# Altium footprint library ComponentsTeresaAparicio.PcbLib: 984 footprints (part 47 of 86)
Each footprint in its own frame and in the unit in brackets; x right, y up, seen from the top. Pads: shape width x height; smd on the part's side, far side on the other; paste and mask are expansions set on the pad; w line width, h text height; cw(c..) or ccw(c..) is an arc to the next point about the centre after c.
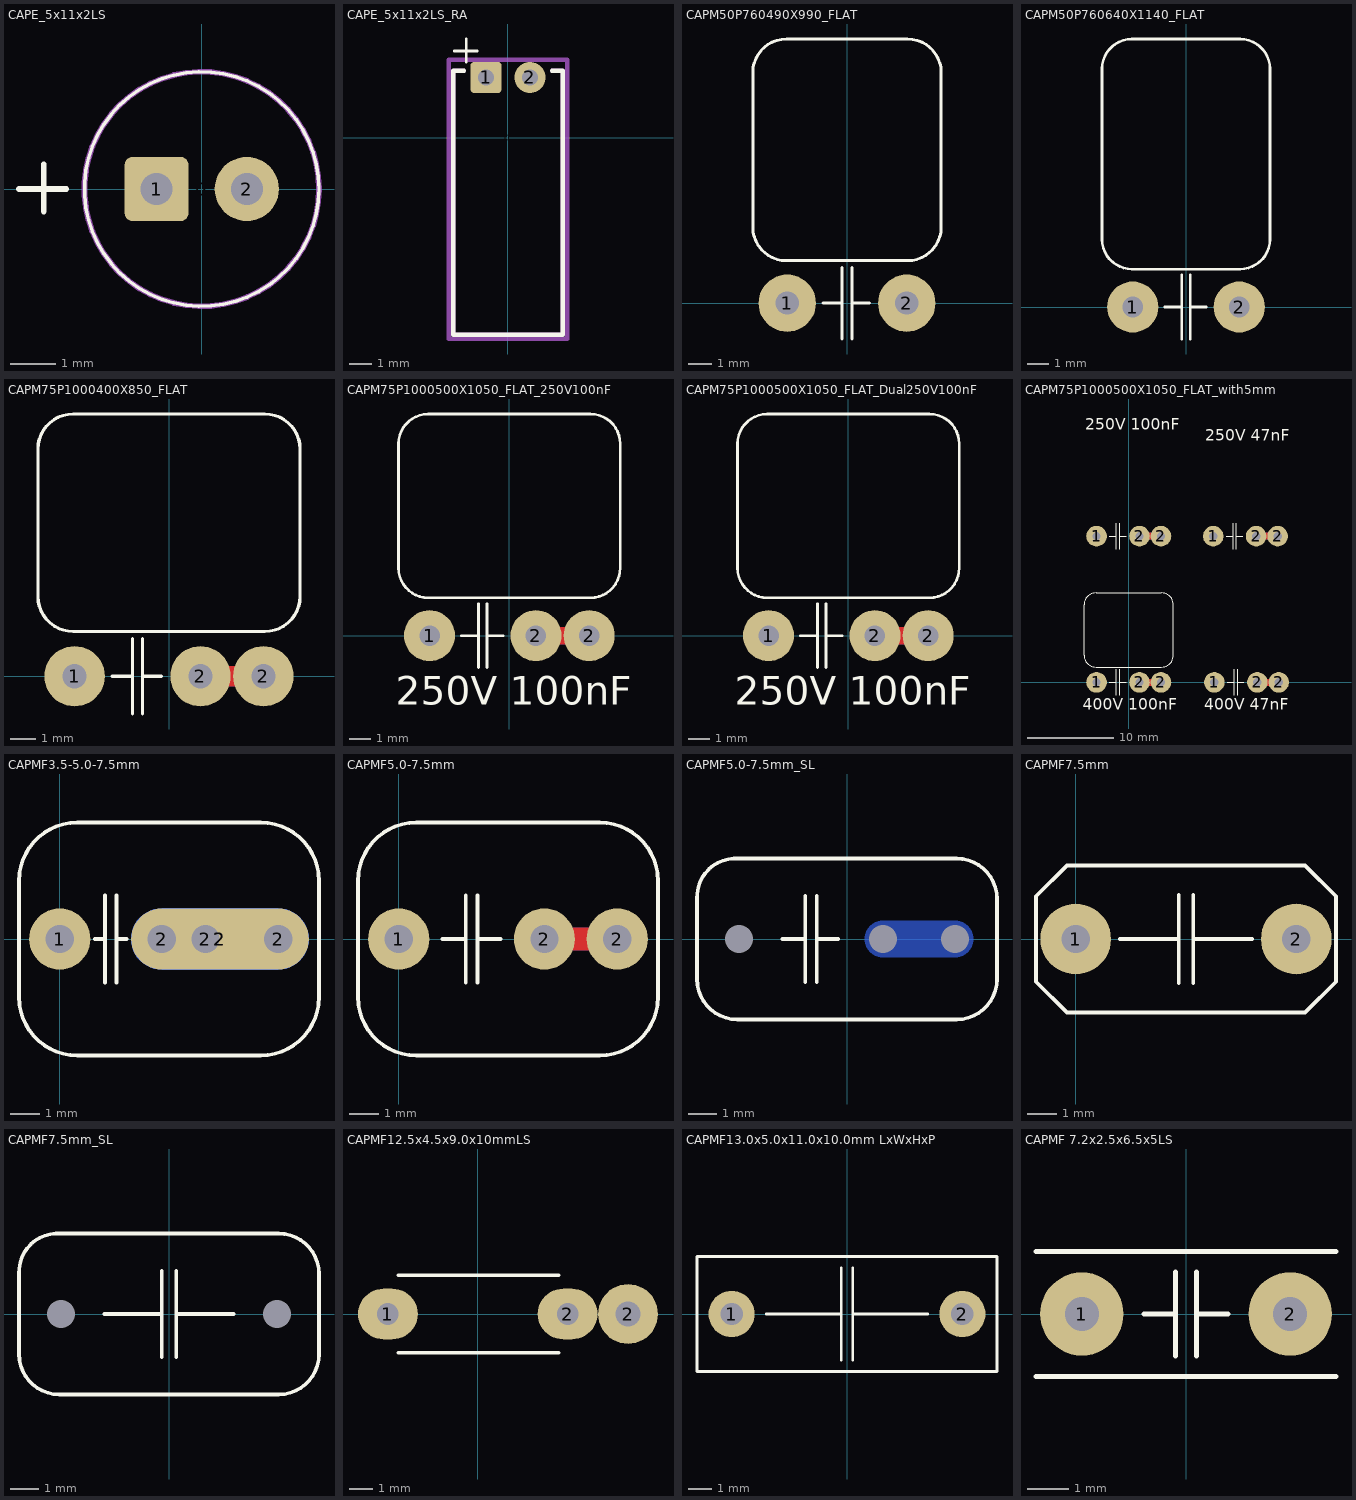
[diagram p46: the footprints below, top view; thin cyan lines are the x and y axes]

## CAPE_5x11x2LS [mil] "Capacitor, electrolytic, radial can"
height 433.07
pads (3):
  round 39.37 on Mech14: 0(0,0)
  rrect25% 56x56 hole 28: 1(-39.37,0)
  round 56 hole 28: 2(39.37,0)
Top Overlay:
  circle w3: c0,0 r102.36
  lines w5: -159.45,0 -118.11,0 ; -137.8,-19.68 -137.8,21.65
Mechanical 13:
  circle w5: c0,0 r102.36
3D body: height 433.07, standoff -86.61, extent -98.42,-98.42 98.43,98.43

## CAPE_5x11x2LS_RA [mm] "Capacitor, electrolytic, radial can, laid over"
height 5
pads (3):
  round 0.5 on Mech14: 0(0,0)
  rrect25% 1.422x1.422 hole 0.711: 1(-1,2.75)
  round 1.422 hole 0.711: 2(1,2.75)
Top Overlay:
  lines w0.127: -2.45,3.95 -1.4,3.95 ; -1.9,3.45 -1.9,4.5
  lines w0.2: -2,3.05 -2.5,3.05 -2.5,-8.95 0,-8.95 2.5,-8.95 2.5,3.05 2,3.05
Mechanical 13:
  lines w0.2: -2,3.05 -2.5,3.05 -2.5,-8.95 0,-8.95 2.5,-8.95 2.5,3.05 2,3.05
Mechanical 14:
  lines w0.2: -2.7,-9.15 2.7,-9.15 2.7,3.55 -2.7,3.55 -2.7,-9.15
3D body: height 5.1, standoff -2.2, extent -2.5,-8.947 2.5,3

## CAPM50P760490X990_FLAT [mm] "Capacitor, THT, Metallized Polyester Film with 7.2x4.5x9.5mm LxTxH"
height 4.9
pads (2):
  round 2.4 hole 0.965 unplated: 1(-2.5,0) 2(2.5,0)
Top Overlay:
  lines w0.127: -1,0 -0.2,0 ; -0.2,-1.5 -0.2,1.5 ; 0.2,-1.5 0.2,1.5 ; 0.2,0 0.95,0 ; -3.937,3.175 ccw(c-2.54,3.175) -2.54,1.778 2.54,1.778 ccw(c2.54,3.175) 3.937,3.175 3.937,9.652 ccw(c2.54,9.652) 2.54,11.049 -2.54,11.049 ccw(c-2.54,9.652) -3.937,9.652 -3.937,3.175
3D body: height 4.9, standoff -1.78, extent -3.8,-0.249 3.8,11

## CAPM50P760640X1140_FLAT [mm] "Capacitor, THT, Metallized Polyester Film with 6.0x11.0x7.2mm TxHxW"
height 6.4
pads (2):
  round 2.4 hole 0.965 unplated: 1(-2.5,0) 2(2.5,0)
Top Overlay:
  lines w0.127: -1,0 -0.2,0 ; -0.2,-1.5 -0.2,1.5 ; 0.2,-1.5 0.2,1.5 ; 0.2,0 0.95,0 ; -3.937,3.175 ccw(c-2.54,3.175) -2.54,1.778 2.54,1.778 ccw(c2.54,3.175) 3.937,3.175 3.937,11.176 ccw(c2.54,11.176) 2.54,12.573 -2.54,12.573 ccw(c-2.54,11.176) -3.937,11.176 -3.937,3.175
3D body: height 6.4, standoff -1.78, extent -3.8,-0.249 3.8,12.5

## CAPM75P1000400X850_FLAT [mm] "Capacitor, THT, Metallized Polyester Film with 3.5x9.5x10.0mm TxHxW"
height 3.5
pads (3):
  round 2.4 hole 0.965 unplated: 1(-3.75,0) 2(1.25,0) 2(3.75,0)
Top Layer:
  lines w0.813: 1.25,0 3.75,0
Bottom Layer:
  lines w0.813: 1.25,0 3.75,0
Top Overlay:
  lines w0.127: -2.25,0 -1.45,0 ; -1.45,-1.5 -1.45,1.5 ; -1.05,-1.5 -1.05,1.5 ; -1.05,0 -0.3,0 ; -5.207,3.175 ccw(c-3.81,3.175) -3.81,1.778 3.81,1.778 ccw(c3.81,3.175) 5.207,3.175 5.207,9.017 ccw(c3.81,9.017) 3.81,10.414 -3.81,10.414 ccw(c-3.81,9.017) -5.207,9.017 -5.207,3.175
3D body: height 4, standoff -1.78, extent -5,-0.249 5,9.6

## CAPM75P1000500X1050_FLAT_250V100nF [mm] "Capacitor, THT, Metallized Polyester Film with 3.5x9.5x10.0mm TxHxW"
height 3.5
pads (3):
  round 2.4 hole 0.965 unplated: 1(-3.75,0) 2(1.25,0) 2(3.75,0)
Top Layer:
  lines w0.813: 1.25,0 3.75,0
Bottom Layer:
  lines w0.813: 1.25,0 3.75,0
Top Overlay:
  lines w0.127: -2.25,0 -1.45,0 ; -1.45,-1.5 -1.45,1.5 ; -1.05,-1.5 -1.05,1.5 ; -1.05,0 -0.3,0 ; -5.207,3.175 ccw(c-3.81,3.175) -3.81,1.778 3.81,1.778 ccw(c3.81,3.175) 5.207,3.175 5.207,9.017 ccw(c3.81,9.017) 3.81,10.414 -3.81,10.414 ccw(c-3.81,9.017) -5.207,9.017 -5.207,3.175
  text "250V 100nF" at -5.334,-3.683 h2.29
3D body: height 4, standoff -1.78, extent -5,-0.249 5,9.6
3D body: height 4.5, standoff -1.78, extent -4.92,-0.249 2.38,10.6

## CAPM75P1000500X1050_FLAT_Dual250V100nF [mm] "Capacitor, THT, Metallized Polyester Film with 3.5x9.5x10.0mm TxHxW"
height 3.5
pads (3):
  round 2.4 hole 0.965 unplated: 1(-3.75,0) 2(1.25,0) 2(3.75,0)
Top Layer:
  lines w0.813: 1.25,0 3.75,0
Bottom Layer:
  lines w0.813: 1.25,0 3.75,0
Top Overlay:
  lines w0.127: -2.25,0 -1.45,0 ; -1.45,-1.5 -1.45,1.5 ; -1.05,-1.5 -1.05,1.5 ; -1.05,0 -0.3,0 ; -5.207,3.175 ccw(c-3.81,3.175) -3.81,1.778 3.81,1.778 ccw(c3.81,3.175) 5.207,3.175 5.207,9.017 ccw(c3.81,9.017) 3.81,10.414 -3.81,10.414 ccw(c-3.81,9.017) -5.207,9.017 -5.207,3.175
  text "250V 100nF" at -5.334,-3.683 h2.29
3D body: height 4.2, standoff -1.78, extent -4.5,-0.249 4.5,9.6
3D body: height 5.7, standoff -1.78, extent -4.5,-0.249 2,10.1
3D body: height 5.4, standoff -1.78, extent -5.05,-0.249 2.55,11.5
3D body: height 4.5, standoff -1.78, extent -4.9,-0.249 2.4,10.6
3D body: height 4, standoff -1.78, extent -5,-0.249 5,9.6

## CAPM75P1000500X1050_FLAT_with5mm [mm] "Capacitor, THT, Metallized Polyester Film with 3.5x9.5x10.0mm TxHxW"
height 3.5
pads (12):
  round 2.4 hole 0.965 unplated: 1(-3.75,0) 1(-3.75,17.018) 1(9.839,17.018) 1(9.966,0) 2(1.25,0) 2(1.25,17.018) 2(3.75,0) 2(3.75,17.018) 2(14.839,17.018) 2(14.966,0) 2(17.339,17.018) 2(17.466,0)
Top Layer:
  lines w0.813: 1.25,0 3.75,0 ; 1.25,17.018 3.75,17.018 ; 14.839,17.018 17.339,17.018 ; 14.966,0 17.466,0
Bottom Layer:
  lines w0.813: 1.25,0 3.75,0 ; 1.25,17.018 3.75,17.018 ; 14.839,17.018 17.339,17.018 ; 14.966,0 17.466,0
Top Overlay:
  lines w0.127: -2.25,0 -1.45,0 ; -2.25,17.018 -1.45,17.018 ; -1.45,-1.5 -1.45,1.5 ; -1.45,15.518 -1.45,18.518 ; -1.05,-1.5 -1.05,1.5 ; -1.05,0 -0.3,0 ; -1.05,15.518 -1.05,18.518 ; -1.05,17.018 -0.3,17.018 ; 11.339,17.018 12.139,17.018 ; 11.466,0 12.266,0 ; 12.139,15.518 12.139,18.518 ; 12.266,-1.5 12.266,1.5 ; 12.539,15.518 12.539,18.518 ; 12.539,17.018 13.289,17.018 ; 12.666,-1.5 12.666,1.5 ; 12.666,0 13.416,0 ; -5.207,3.175 ccw(c-3.81,3.175) -3.81,1.778 3.81,1.778 ccw(c3.81,3.175) 5.207,3.175 5.207,9.017 ccw(c3.81,9.017) 3.81,10.414 -3.81,10.414 ccw(c-3.81,9.017) -5.207,9.017 -5.207,3.175
  text "400V 100nF" at -5.334,-3.683 h2.29
  text "400V 47nF" at 8.763,-3.683 h2.29
  text "250V 100nF" at -5.08,28.956 h2.29
  text "250V 47nF" at 8.89,27.686 h2.29
3D body: height 4, standoff -1.78, extent -5,16.769 5,26.618
3D body: height 4.5, standoff -1.78, extent -4.92,16.769 2.38,27.618
3D body: height 3.5, standoff -1.78, extent 8.719,16.769 15.919,26.118
3D body: height 2.5, standoff -1.78, extent 8.589,16.769 18.589,25.118
3D body: height 4, standoff -1.78, extent 8.716,-0.249 18.716,9.6
3D body: height 4.5, standoff -1.78, extent 8.796,-0.249 16.096,10.6
3D body: height 5, standoff -1.78, extent -5,-0.249 5,11.6
3D body: height 7.8, standoff -1.78, extent -5.17,-0.249 2.63,14.1

## CAPMF3.5-5.0-7.5mm [mm] "Capacitor, THT, Metallized Polyester Film, 3.5 & 5.0 & 7.5mm pitch hybrid"
height 10
pads (6):
  round 2.1 hole 0.965: 1(0,0)
  round 1.5 hole 0.965: 2(3.5,0) 2(5,0) 2(7.5,0)
  oval 6.1x2.1 smd: 2(5.5,0)
  oval 6.1x2.1 smd far side: 2(5.5,0)
Top Overlay:
  lines w0.127: 1.2,0 1.55,0 ; 1.55,-1.5 1.55,1.5 ; 1.95,-1.5 1.95,1.5 ; 1.95,0 2.3,0 ; -1.4,-2 ccw(c0.6,-2) 0.6,-4 6.9,-4 ccw(c6.9,-2) 8.9,-2 8.9,2 ccw(c6.9,2) 6.9,4 0.6,4 ccw(c0.6,2) -1.4,2 -1.4,-2
3D body: height 11, standoff -2.54, extent -1.25,-4 8.75,4

## CAPMF5.0-7.5mm [mm] "Capacitor, THT, Metallized Polyester Film, 5 & 7.5mm pitch hybrid"
height 10
pads (3):
  round 2.1 hole 0.965: 1(0,0) 2(5,0) 2(7.5,0)
Top Layer:
  lines w0.8: 5,0 7.5,0
Bottom Layer:
  lines w0.8: 5,0 7.5,0
Top Overlay:
  lines w0.127: 1.5,0 2.3,0 ; 2.3,-1.5 2.3,1.5 ; 2.7,-1.5 2.7,1.5 ; 2.7,0 3.5,0 ; -1.4,-2 ccw(c0.6,-2) 0.6,-4 6.9,-4 ccw(c6.9,-2) 8.9,-2 8.9,2 ccw(c6.9,2) 6.9,4 0.6,4 ccw(c0.6,2) -1.4,2 -1.4,-2
3D body: height 11, standoff -2.54, extent -1.25,-4 8.75,4

## CAPMF5.0-7.5mm_SL [mm] "Capacitor, THT, Metallized Polyester Film"
height 9
pads (3):
  round 0 / inner round 0 / far side round 2.4 hole 0.965 unplated: 1(-3.75,0) 2(1.25,0) 2(3.75,0)
Bottom Layer:
  lines w1.27: 1.25,0 3.75,0
Top Overlay:
  lines w0.127: -2.25,0 -1.45,0 ; -1.45,-1.5 -1.45,1.5 ; -1.05,-1.5 -1.05,1.5 ; -1.05,0 -0.3,0 ; -5.207,-1.397 ccw(c-3.81,-1.397) -3.81,-2.794 3.81,-2.794 ccw(c3.81,-1.397) 5.207,-1.397 5.207,1.397 ccw(c3.81,1.397) 3.81,2.794 -3.937,2.794 ccw(c-3.873,1.46) -5.207,1.397 -5.207,-1.397
3D body: height 9, standoff -2.54, extent -5.25,-3 5.25,3

## CAPMF7.5mm [mm] "Capacitor, THT, Metallized Polyester Film"
height 10
pads (2):
  round 2.4 hole 0.965: 1(0,0) 2(7.5,0)
Top Overlay:
  lines w0.127: 1.5,0 3.5,0 ; 3.5,-1.5 3.5,1.5 ; 4,-1.5 4,1.5 ; 4,0 6,0 ; -1.35,-1.45 -0.3,-2.5 7.8,-2.5 8.85,-1.45 8.85,1.45 7.8,2.5 -0.3,2.5 -1.35,1.45 -1.35,-1.45
3D body: height 10, standoff 0.5, extent -1.359,-2.509 8.859,2.509

## CAPMF7.5mm_SL [mm] "Capacitor, THT, Metallized Polyester Film"
height 9
pads (2):
  round 0 / inner round 0 / far side round 2.4 hole 0.965 unplated: 1(-3.75,0) 2(3.75,0)
Top Overlay:
  lines w0.127: -2.25,0 -0.25,0 ; -0.25,-1.5 -0.25,1.5 ; 0.25,-1.5 0.25,1.5 ; 0.25,0 2.25,0 ; -5.207,-1.397 ccw(c-3.81,-1.397) -3.81,-2.794 3.81,-2.794 ccw(c3.81,-1.397) 5.207,-1.397 5.207,1.397 ccw(c3.81,1.397) 3.81,2.794 -3.937,2.794 ccw(c-3.873,1.46) -5.207,1.397 -5.207,-1.397
3D body: height 9, standoff -2.54, extent -5,-2.75 5,2.75

## CAPMF12.5x4.5x9.0x10mmLS [mil] "Capacitor, MF, Thru-Hole, Dipped Radial; Body 12.5 x 4.5 x 9.0 mm (WxTxH) Pin Spacing 10.0 mm (typ)"
height 354.33
pads (3):
  oval 100x85 hole 36: 1(-150,0) 2(150,0)
  round 100 hole 42: 2(251,0)
Top Overlay:
  lines w6: -132.72,-65 135,-65 ; -132.72,65 135,65
3D body: height 354.33, standoff -100, extent -196.06,-88.58 296.07,88.59

## CAPMF13.0x5.0x11.0x10.0mm LxWxHxP [mm] "Capacitor, THT, Metallized Polypropylene Film, 10mm lead pitch"
height 11
pads (2):
  round 2 hole 0.965: 1(-5,0) 2(5,0)
Top Overlay:
  lines w0.127: -3.5,0 -0.25,0 ; -0.25,-2 -0.25,2 ; 0.25,-2 0.25,2 ; 0.25,0 3.5,0 ; -6.5,-2.5 -6.5,2.5 6.5,2.5 6.5,-2.5 -6.5,-2.5
3D body: height 11, standoff 0, extent -6.5,-2.5 6.5,2.5

## CAPMF 7.2x2.5x6.5x5LS [mm] "Capacitor, THT, Metallized Polyester Film"
height 8.2
pads (2):
  round 2 hole 0.813: 1(-2.5,0) 2(2.5,0)
Top Overlay:
  lines w0.127: -3.6,-1.5 3.6,-1.5 ; -3.6,1.5 3.6,1.5 ; -1,0 -0.25,0 ; -0.25,-1 -0.25,1 ; 0.25,-1 0.25,1 ; 0.25,0 1,0
3D body: height 7.5, standoff -2, extent -3.6,-1.25 3.6,1.25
